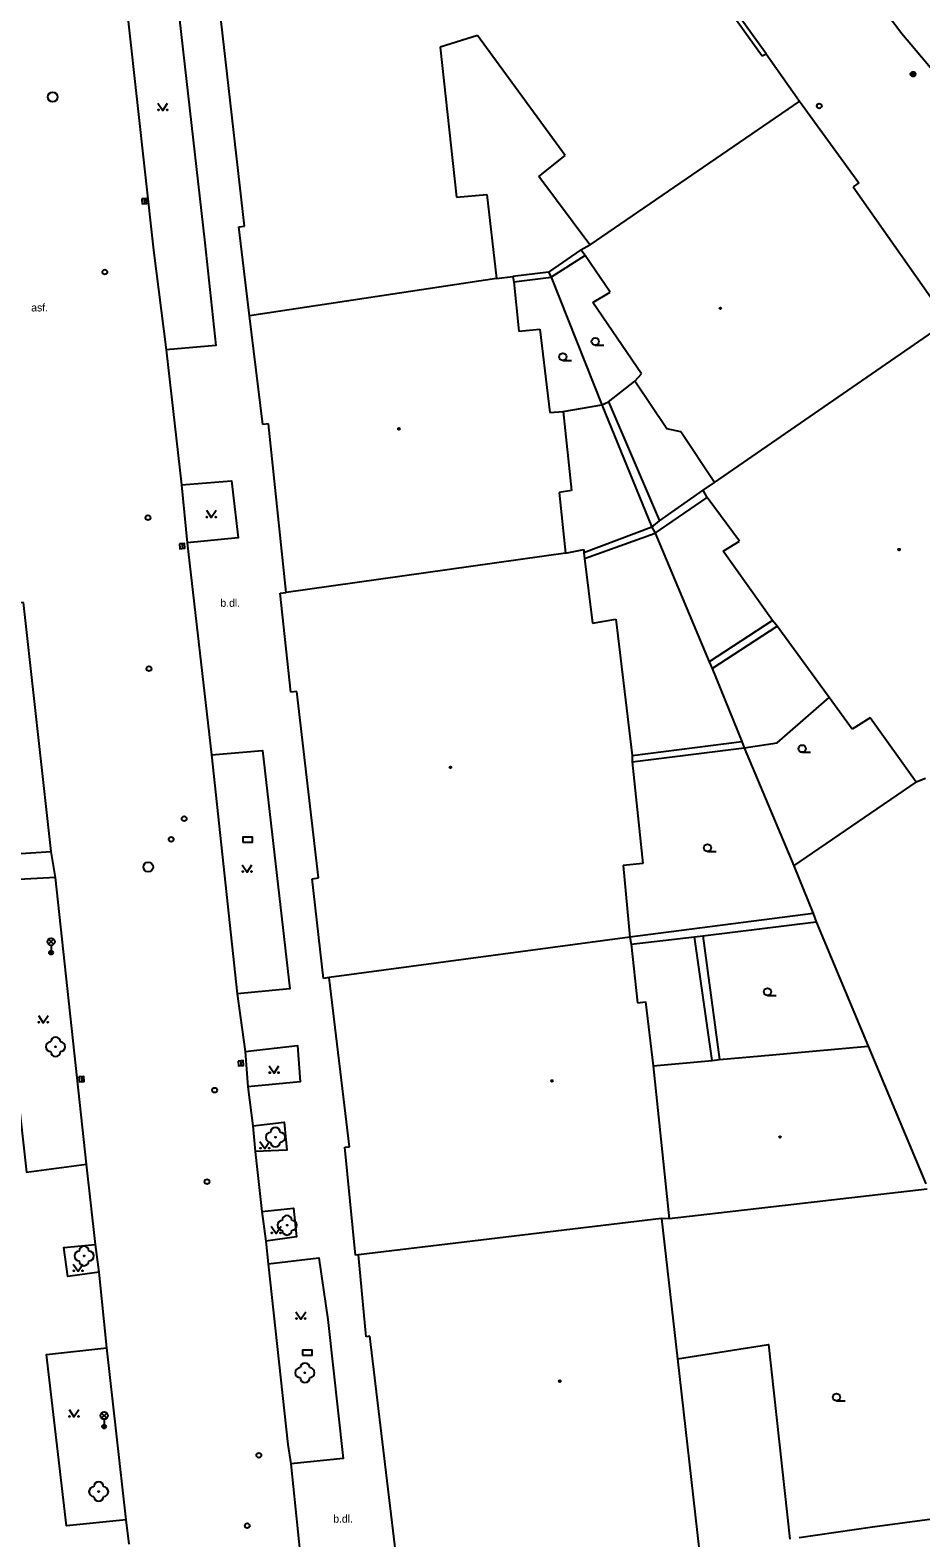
# Model space of a CAD drawing. Extents: x -599770 to -598493, y -1162076 to -1159209.
# Drawn here: x -598969.3 to -598923.5, y -1159761.3 to -1159683.6 of the extents above; entities that cross this region are included whole.
import ezdxf

# ---------------------------------------------------------------- set-up
doc = ezdxf.new("R2010")
doc.units = 0
doc.layers.add('Podklad', color=7, linetype='Continuous')

msp = doc.modelspace()

# ---------------------------------------------------------------- linework, layer by layer
at = {"layer": 'Podklad'}
for p, q in [((-598963.48, -1159692.285), (-598963.46, -1159692.535)), ((-598940.25, -1159699.828), (-598939.812, -1159699.828)), ((-598941.92, -1159700.617), (-598941.483, -1159700.617)), ((-598961.53, -1159710.055), (-598961.51, -1159710.305)), ((-598929.6, -1159720.808), (-598929.163, -1159720.808)), ((-598934.47, -1159725.918), (-598934.032, -1159725.918)), ((-598968.402, -1159730.7), (-598968.137, -1159730.435)), ((-598968.402, -1159730.435), (-598968.137, -1159730.7)), ((-598968.27, -1159730.755), (-598968.27, -1159731.13)), ((-598931.38, -1159733.337), (-598930.942, -1159733.337)), ((-598958.51, -1159736.705), (-598958.49, -1159736.955)), ((-598966.71, -1159737.525), (-598966.69, -1159737.775)), ((-598927.83, -1159754.227), (-598927.392, -1159754.227)), ((-598965.672, -1159755.12), (-598965.407, -1159754.855)), ((-598965.672, -1159754.855), (-598965.407, -1159755.12)), ((-598965.54, -1159755.175), (-598965.54, -1159755.55))]:
    msp.add_line(p, q, dxfattribs=at)
for points in [[(-598963.63, -1159666.07), (-598962.53, -1159675.33), (-598960.36, -1159694.56), (-598959.79, -1159699.84), (-598962.35, -1159700.07)], [(-598944.31, -1159667.32), (-598931.66, -1159684.92)], [(-598931.45, -1159684.82), (-598944.12, -1159667.22)], [(-598932.16, -1159673.51), (-598924.47, -1159683.77)], [(-598965.14, -1159675.51), (-598962.99, -1159694.93)], [(-598958.31, -1159693.7), (-598960.4, -1159675.27)], [(-598946.32, -1159683.87), (-598948.24, -1159684.48)], [(-598941.8, -1159690.06), (-598946.32, -1159683.87)], [(-598924.47, -1159683.77), (-598919.12, -1159690.13)], [(-598948.24, -1159684.48), (-598947.4, -1159692.2)], [(-598931.66, -1159684.92), (-598931.45, -1159684.82)], [(-598931.45, -1159684.82), (-598929.73, -1159687.25)], [(-598962.77, -1159687.355), (-598962.52, -1159687.73), (-598962.27, -1159687.355)], [(-598929.73, -1159687.25), (-598940.53, -1159694.66)], [(-598929.73, -1159687.25), (-598926.68, -1159691.47)], [(-598943.15, -1159691.13), (-598941.8, -1159690.06)], [(-598940.53, -1159694.66), (-598943.15, -1159691.13)], [(-598926.68, -1159691.47), (-598926.97, -1159691.66)], [(-598926.97, -1159691.66), (-598922.1, -1159698.6)], [(-598947.4, -1159692.2), (-598945.83, -1159692.06)], [(-598945.83, -1159692.06), (-598945.33, -1159696.4)], [(-598958.61, -1159693.73), (-598958.31, -1159693.7)], [(-598958.06, -1159698.32), (-598958.61, -1159693.73)], [(-598962.99, -1159694.93), (-598962.35, -1159700.07)], [(-598940.99, -1159694.91), (-598942.66, -1159696.07)], [(-598940.99, -1159694.91), (-598940.53, -1159694.66)], [(-598940.78, -1159695.2), (-598940.99, -1159694.91)], [(-598940.78, -1159695.2), (-598942.53, -1159696.33)], [(-598939.49, -1159697.1), (-598940.78, -1159695.2)], [(-598945.33, -1159696.4), (-598958.06, -1159698.32)], [(-598945.33, -1159696.4), (-598944.49, -1159696.29)], [(-598942.66, -1159696.07), (-598944.49, -1159696.29)], [(-598944.49, -1159696.29), (-598944.45, -1159696.56)], [(-598944.45, -1159696.56), (-598942.53, -1159696.33)], [(-598942.66, -1159696.07), (-598942.53, -1159696.33)], [(-598942.53, -1159696.33), (-598939.92, -1159702.91)], [(-598944.45, -1159696.56), (-598944.19, -1159699.1)], [(-598940.37, -1159697.63), (-598939.49, -1159697.1)], [(-598937.87, -1159701.3), (-598940.37, -1159697.63)], [(-598957.37, -1159703.91), (-598958.06, -1159698.32)], [(-598934.12, -1159706.9), (-598922.1, -1159698.6)], [(-598944.19, -1159699.1), (-598943.11, -1159699.01)], [(-598943.11, -1159699.01), (-598942.59, -1159703.3)], [(-598962.35, -1159700.07), (-598961.55, -1159707.03)], [(-598939.57, -1159702.74), (-598938.22, -1159701.68)], [(-598938.22, -1159701.68), (-598937.87, -1159701.3)], [(-598936.56, -1159704.13), (-598938.22, -1159701.68)], [(-598942.59, -1159703.3), (-598941.9, -1159703.24)], [(-598941.9, -1159703.24), (-598939.92, -1159702.91)], [(-598941.9, -1159703.24), (-598941.48, -1159707.31)], [(-598939.92, -1159702.91), (-598939.57, -1159702.74)], [(-598939.92, -1159702.91), (-598937.34, -1159709.21)], [(-598939.57, -1159702.74), (-598936.94, -1159708.88)], [(-598957.07, -1159703.88), (-598957.37, -1159703.91)], [(-598956.17, -1159712.57), (-598957.07, -1159703.88)], [(-598935.84, -1159704.29), (-598936.56, -1159704.13)], [(-598934.12, -1159706.9), (-598935.84, -1159704.29)], [(-598961.55, -1159707.03), (-598958.98, -1159706.81), (-598958.63, -1159709.76), (-598961.26, -1159710.01)], [(-598961.55, -1159707.03), (-598961.26, -1159710.01)], [(-598941.48, -1159707.31), (-598942.11, -1159707.42)], [(-598936.94, -1159708.88), (-598934.7, -1159707.3)], [(-598934.7, -1159707.3), (-598934.12, -1159706.9)], [(-598934.49, -1159707.68), (-598934.7, -1159707.3)], [(-598942.11, -1159707.42), (-598941.79, -1159710.54)], [(-598937.17, -1159709.52), (-598934.49, -1159707.68)], [(-598932.83, -1159709.92), (-598934.49, -1159707.68)], [(-598960.27, -1159708.335), (-598960.02, -1159708.71), (-598959.77, -1159708.335)], [(-598937.34, -1159709.21), (-598936.94, -1159708.88)], [(-598937.34, -1159709.21), (-598940.84, -1159710.52)], [(-598940.8, -1159710.82), (-598937.17, -1159709.52)], [(-598937.34, -1159709.21), (-598937.17, -1159709.52)], [(-598937.17, -1159709.52), (-598934.38, -1159716.15)], [(-598961.26, -1159710.01), (-598960.01, -1159720.94)], [(-598941.79, -1159710.54), (-598940.84, -1159710.36)], [(-598940.84, -1159710.36), (-598940.84, -1159710.52)], [(-598933.66, -1159710.45), (-598932.83, -1159709.92)], [(-598931.13, -1159714.01), (-598933.66, -1159710.45)], [(-598941.79, -1159710.54), (-598956.17, -1159712.57)], [(-598940.84, -1159710.52), (-598940.8, -1159710.82)], [(-598940.8, -1159710.82), (-598940.4, -1159714.15)], [(-598956.47, -1159712.6), (-598956.17, -1159712.57)], [(-598955.92, -1159717.7), (-598956.47, -1159712.6)], [(-598969.69, -1159713.09), (-598972.8, -1159713.42), (-598971.4, -1159726.13), (-598968.26, -1159725.91)], [(-598968.26, -1159725.91), (-598969.69, -1159713.09)], [(-598940.4, -1159714.15), (-598939.2, -1159713.94)], [(-598939.2, -1159713.94), (-598938.36, -1159720.98)], [(-598931.13, -1159714.01), (-598934.38, -1159716.15)], [(-598934.24, -1159716.49), (-598930.88, -1159714.31)], [(-598930.88, -1159714.31), (-598931.13, -1159714.01)], [(-598927.02, -1159719.61), (-598928.21, -1159717.98), (-598930.88, -1159714.31)], [(-598934.38, -1159716.15), (-598934.24, -1159716.49)], [(-598934.24, -1159716.49), (-598932.71, -1159720.25)], [(-598955.62, -1159717.67), (-598955.92, -1159717.7)], [(-598954.51, -1159727.28), (-598955.62, -1159717.67)], [(-598932.58, -1159720.57), (-598930.89, -1159720.32), (-598928.21, -1159717.98)], [(-598926.1, -1159719.03), (-598927.02, -1159719.61)], [(-598923.73, -1159722.34), (-598926.1, -1159719.03)], [(-598938.36, -1159720.98), (-598932.71, -1159720.25)], [(-598938.35, -1159721.3), (-598932.58, -1159720.57)], [(-598932.71, -1159720.25), (-598932.58, -1159720.57)], [(-598932.58, -1159720.57), (-598930.02, -1159726.66)], [(-598960.01, -1159720.94), (-598957.39, -1159720.71), (-598955.98, -1159732.99), (-598958.69, -1159733.25)], [(-598960.01, -1159720.94), (-598958.69, -1159733.25)], [(-598938.36, -1159720.98), (-598938.35, -1159721.3)], [(-598938.35, -1159721.3), (-598937.8, -1159726.53)], [(-598930.02, -1159726.66), (-598923.73, -1159722.34)], [(-598923.25, -1159722.16), (-598923.73, -1159722.34)], [(-598968.05, -1159727.25), (-598968.26, -1159725.91)], [(-598958.43, -1159726.605), (-598958.18, -1159726.98), (-598957.93, -1159726.605)], [(-598937.8, -1159726.53), (-598938.82, -1159726.64)], [(-598938.82, -1159726.64), (-598938.47, -1159730.34)], [(-598930.02, -1159726.66), (-598929.04, -1159729.12)], [(-598968.05, -1159727.25), (-598971.21, -1159727.43), (-598969.54, -1159742.44), (-598966.44, -1159742.03)], [(-598966.44, -1159742.03), (-598968.05, -1159727.25)], [(-598954.82, -1159727.33), (-598954.51, -1159727.28)], [(-598954.25, -1159732.46), (-598954.82, -1159727.33)], [(-598929.04, -1159729.12), (-598938.47, -1159730.34)], [(-598929.04, -1159729.12), (-598928.88, -1159729.55)], [(-598934.72, -1159730.27), (-598928.88, -1159729.55)], [(-598928.88, -1159729.55), (-598926.2, -1159735.95)], [(-598938.47, -1159730.34), (-598953.95, -1159732.41)], [(-598938.47, -1159730.34), (-598938.4, -1159730.7)], [(-598938.4, -1159730.7), (-598935.14, -1159730.32)], [(-598935.14, -1159730.32), (-598934.72, -1159730.27)], [(-598934.24, -1159736.68), (-598935.14, -1159730.32)], [(-598934.72, -1159730.27), (-598933.85, -1159736.64)], [(-598938.4, -1159730.7), (-598938.07, -1159733.71)], [(-598953.95, -1159732.41), (-598954.25, -1159732.46)], [(-598952.9, -1159741.13), (-598953.95, -1159732.41)], [(-598958.69, -1159733.25), (-598958.27, -1159736.23)], [(-598938.07, -1159733.71), (-598937.67, -1159733.66)], [(-598937.67, -1159733.66), (-598937.27, -1159736.96)], [(-598968.92, -1159734.365), (-598968.67, -1159734.74), (-598968.42, -1159734.365)], [(-598958.27, -1159736.23), (-598955.58, -1159735.92), (-598955.45, -1159737.78), (-598958.14, -1159738.05)], [(-598929.07, -1159736.21), (-598926.2, -1159735.95)], [(-598926.2, -1159735.95), (-598923.23, -1159743.05)], [(-598958.27, -1159736.23), (-598958.14, -1159738.05)], [(-598937.27, -1159736.96), (-598934.24, -1159736.68)], [(-598934.24, -1159736.68), (-598933.85, -1159736.64)], [(-598933.85, -1159736.64), (-598931.12, -1159736.39)], [(-598931.12, -1159736.39), (-598929.07, -1159736.21)], [(-598957.04, -1159736.965), (-598956.79, -1159737.34), (-598956.54, -1159736.965)], [(-598937.27, -1159736.96), (-598936.45, -1159744.84)], [(-598958.14, -1159738.05), (-598957.89, -1159740.06)], [(-598957.89, -1159740.06), (-598956.27, -1159739.86), (-598956.13, -1159741.31), (-598957.77, -1159741.38)], [(-598957.89, -1159740.06), (-598957.77, -1159741.38)], [(-598957.77, -1159741.38), (-598957.42, -1159744.47)], [(-598957.52, -1159740.855), (-598957.27, -1159741.23), (-598957.02, -1159740.855)], [(-598953.15, -1159741.16), (-598952.9, -1159741.13)], [(-598952.6, -1159746.72), (-598953.15, -1159741.16)], [(-598965.99, -1159746.17), (-598966.44, -1159742.03)], [(-598923.17, -1159743.32), (-598936.45, -1159744.84)], [(-598957.42, -1159744.47), (-598955.79, -1159744.29), (-598955.64, -1159745.77), (-598957.22, -1159745.99)], [(-598957.42, -1159744.47), (-598957.22, -1159745.99)], [(-598956.93, -1159745.225), (-598956.68, -1159745.6), (-598956.43, -1159745.225)], [(-598936.84, -1159744.83), (-598952.45, -1159746.7)], [(-598936.45, -1159744.84), (-598936.84, -1159744.83)], [(-598936.84, -1159744.83), (-598936.01, -1159752.06)], [(-598965.79, -1159747.59), (-598967.41, -1159747.81), (-598967.61, -1159746.33), (-598965.99, -1159746.17)], [(-598965.79, -1159747.59), (-598965.99, -1159746.17)], [(-598957.22, -1159745.99), (-598957.09, -1159747.17)], [(-598957.09, -1159747.17), (-598954.49, -1159746.85), (-598954.02, -1159750.03), (-598953.23, -1159757.19), (-598955.93, -1159757.47)], [(-598952.45, -1159746.7), (-598952.6, -1159746.72)], [(-598952.05, -1159750.92), (-598952.45, -1159746.7)], [(-598967.13, -1159747.175), (-598966.88, -1159747.55), (-598966.63, -1159747.175)], [(-598965.4, -1159751.5), (-598965.79, -1159747.59)], [(-598957.09, -1159747.17), (-598956.08, -1159756.48), (-598955.93, -1159757.47)], [(-598955.66, -1159749.635), (-598955.41, -1159750.01), (-598955.16, -1159749.635)], [(-598964.41, -1159760.36), (-598967.48, -1159760.66), (-598968.5, -1159751.84), (-598965.4, -1159751.5)], [(-598964.41, -1159760.36), (-598965.4, -1159751.5)], [(-598951.86, -1159750.9), (-598952.05, -1159750.92)], [(-598950.31, -1159763.8), (-598951.86, -1159750.9)], [(-598936.01, -1159752.06), (-598931.34, -1159751.33), (-598930.23, -1159761.35)], [(-598936.01, -1159752.06), (-598934.91, -1159761.92)], [(-598967.34, -1159754.675), (-598967.09, -1159755.05), (-598966.84, -1159754.675)], [(-598955.93, -1159757.47), (-598955.2, -1159764.48)], [(-598916.51, -1159759.46), (-598925.97, -1159760.74)], [(-598964.25, -1159761.61), (-598964.41, -1159760.36)], [(-598925.97, -1159760.74), (-598929.76, -1159761.29)]]:
    msp.add_lwpolyline(points, dxfattribs=at)
for points in [[(-598963.604, -1159692.295), (-598963.585, -1159692.544), (-598963.335, -1159692.525), (-598963.355, -1159692.275)], [(-598961.655, -1159710.065), (-598961.635, -1159710.315), (-598961.385, -1159710.295), (-598961.405, -1159710.045)], [(-598958.4, -1159725.435), (-598957.9, -1159725.435), (-598957.9, -1159725.185), (-598958.4, -1159725.185)], [(-598958.635, -1159736.715), (-598958.615, -1159736.965), (-598958.365, -1159736.945), (-598958.385, -1159736.695)], [(-598966.835, -1159737.535), (-598966.815, -1159737.785), (-598966.565, -1159737.765), (-598966.585, -1159737.515)], [(-598955.33, -1159751.865), (-598954.83, -1159751.865), (-598954.83, -1159751.615), (-598955.33, -1159751.615)]]:
    msp.add_lwpolyline(points, close=True, dxfattribs=at)
for centre, radius in [((-598923.89, -1159685.86), 0.125), ((-598923.89, -1159685.86), 0.1), ((-598923.89, -1159685.86), 0.075), ((-598923.89, -1159685.86), 0.05), ((-598923.89, -1159685.86), 0.025), ((-598968.19, -1159687.04), 0.25), ((-598962.745, -1159687.705), 0.025), ((-598962.295, -1159687.705), 0.025), ((-598928.72, -1159687.5), 0.125), ((-598965.5, -1159696.06), 0.125), ((-598933.81, -1159697.93), 0.045), ((-598933.81, -1159697.93), 0.0199), ((-598940.25, -1159699.64), 0.188), ((-598941.92, -1159700.43), 0.188), ((-598950.36, -1159704.14), 0.045), ((-598950.36, -1159704.14), 0.0199), ((-598963.28, -1159708.72), 0.125), ((-598960.245, -1159708.685), 0.025), ((-598959.795, -1159708.685), 0.025), ((-598924.61, -1159710.36), 0.045), ((-598924.61, -1159710.36), 0.0199), ((-598963.23, -1159716.5), 0.125), ((-598929.6, -1159720.62), 0.188), ((-598947.71, -1159721.58), 0.045), ((-598947.71, -1159721.58), 0.0199), ((-598961.42, -1159724.23), 0.125), ((-598962.09, -1159725.29), 0.125), ((-598934.47, -1159725.73), 0.188), ((-598963.27, -1159726.72), 0.25), ((-598958.405, -1159726.955), 0.025), ((-598957.955, -1159726.955), 0.025), ((-598968.27, -1159730.567), 0.188), ((-598968.27, -1159731.13), 0.1), ((-598968.27, -1159731.13), 0.0723), ((-598968.27, -1159731.13), 0.0438), ((-598931.38, -1159733.15), 0.188), ((-598968.895, -1159734.715), 0.025), ((-598968.445, -1159734.715), 0.025), ((-598968.04, -1159735.98), 0.025), ((-598957.015, -1159737.315), 0.025), ((-598956.565, -1159737.315), 0.025), ((-598959.85, -1159738.22), 0.125), ((-598942.48, -1159737.74), 0.045), ((-598942.48, -1159737.74), 0.0199), ((-598956.72, -1159740.64), 0.025), ((-598930.74, -1159740.63), 0.045), ((-598930.74, -1159740.63), 0.0199), ((-598957.495, -1159741.205), 0.025), ((-598957.045, -1159741.205), 0.025), ((-598960.24, -1159742.93), 0.125), ((-598956.12, -1159745.18), 0.025), ((-598956.905, -1159745.575), 0.025), ((-598956.455, -1159745.575), 0.025), ((-598966.57, -1159746.76), 0.025), ((-598967.105, -1159747.525), 0.025), ((-598966.655, -1159747.525), 0.025), ((-598955.635, -1159749.985), 0.025), ((-598955.185, -1159749.985), 0.025), ((-598955.2, -1159752.78), 0.025), ((-598942.08, -1159753.21), 0.045), ((-598942.08, -1159753.21), 0.0199), ((-598927.83, -1159754.04), 0.188), ((-598967.315, -1159755.025), 0.025), ((-598966.865, -1159755.025), 0.025), ((-598965.54, -1159754.988), 0.188), ((-598965.54, -1159755.55), 0.1), ((-598965.54, -1159755.55), 0.0723), ((-598965.54, -1159755.55), 0.0438), ((-598957.57, -1159757.03), 0.125), ((-598965.82, -1159758.9), 0.025), ((-598958.17, -1159760.66), 0.125)]:
    msp.add_circle(centre, radius, dxfattribs=at)
for centre, start, end in [((-598968.29, -1159735.98), 90, 270), ((-598968.04, -1159735.73), 0, 180), ((-598967.79, -1159735.98), 270, 90), ((-598968.04, -1159736.23), 180, 0), ((-598956.97, -1159740.64), 90, 270), ((-598956.72, -1159740.39), 0, 180), ((-598956.47, -1159740.64), 270, 90), ((-598956.72, -1159740.89), 180, 0), ((-598956.37, -1159745.18), 90, 270), ((-598956.12, -1159744.93), 0, 180), ((-598956.12, -1159745.43), 180, 0), ((-598955.87, -1159745.18), 270, 90), ((-598966.82, -1159746.76), 90, 270), ((-598966.57, -1159746.51), 0, 180), ((-598966.32, -1159746.76), 270, 90), ((-598966.57, -1159747.01), 180, 0), ((-598955.2, -1159752.53), 0, 180), ((-598955.45, -1159752.78), 90, 270), ((-598955.2, -1159753.03), 180, 0), ((-598954.95, -1159752.78), 270, 90), ((-598966.07, -1159758.9), 90, 270), ((-598965.82, -1159758.65), 0, 180), ((-598965.57, -1159758.9), 270, 90), ((-598965.82, -1159759.15), 180, 0)]:
    msp.add_arc(centre, 0.25, start, end, dxfattribs=at)

# ---------------------------------------------------------------- texts
for s, p in [('asf.', (-598969.29, -1159698.09)), ('b.dl.', (-598959.55, -1159713.31)), ('b.dl.', (-598953.74, -1159760.5))]:
    msp.add_text(s, height=0.4, dxfattribs=at).set_placement(p)

doc.saveas('drawing.dxf')
